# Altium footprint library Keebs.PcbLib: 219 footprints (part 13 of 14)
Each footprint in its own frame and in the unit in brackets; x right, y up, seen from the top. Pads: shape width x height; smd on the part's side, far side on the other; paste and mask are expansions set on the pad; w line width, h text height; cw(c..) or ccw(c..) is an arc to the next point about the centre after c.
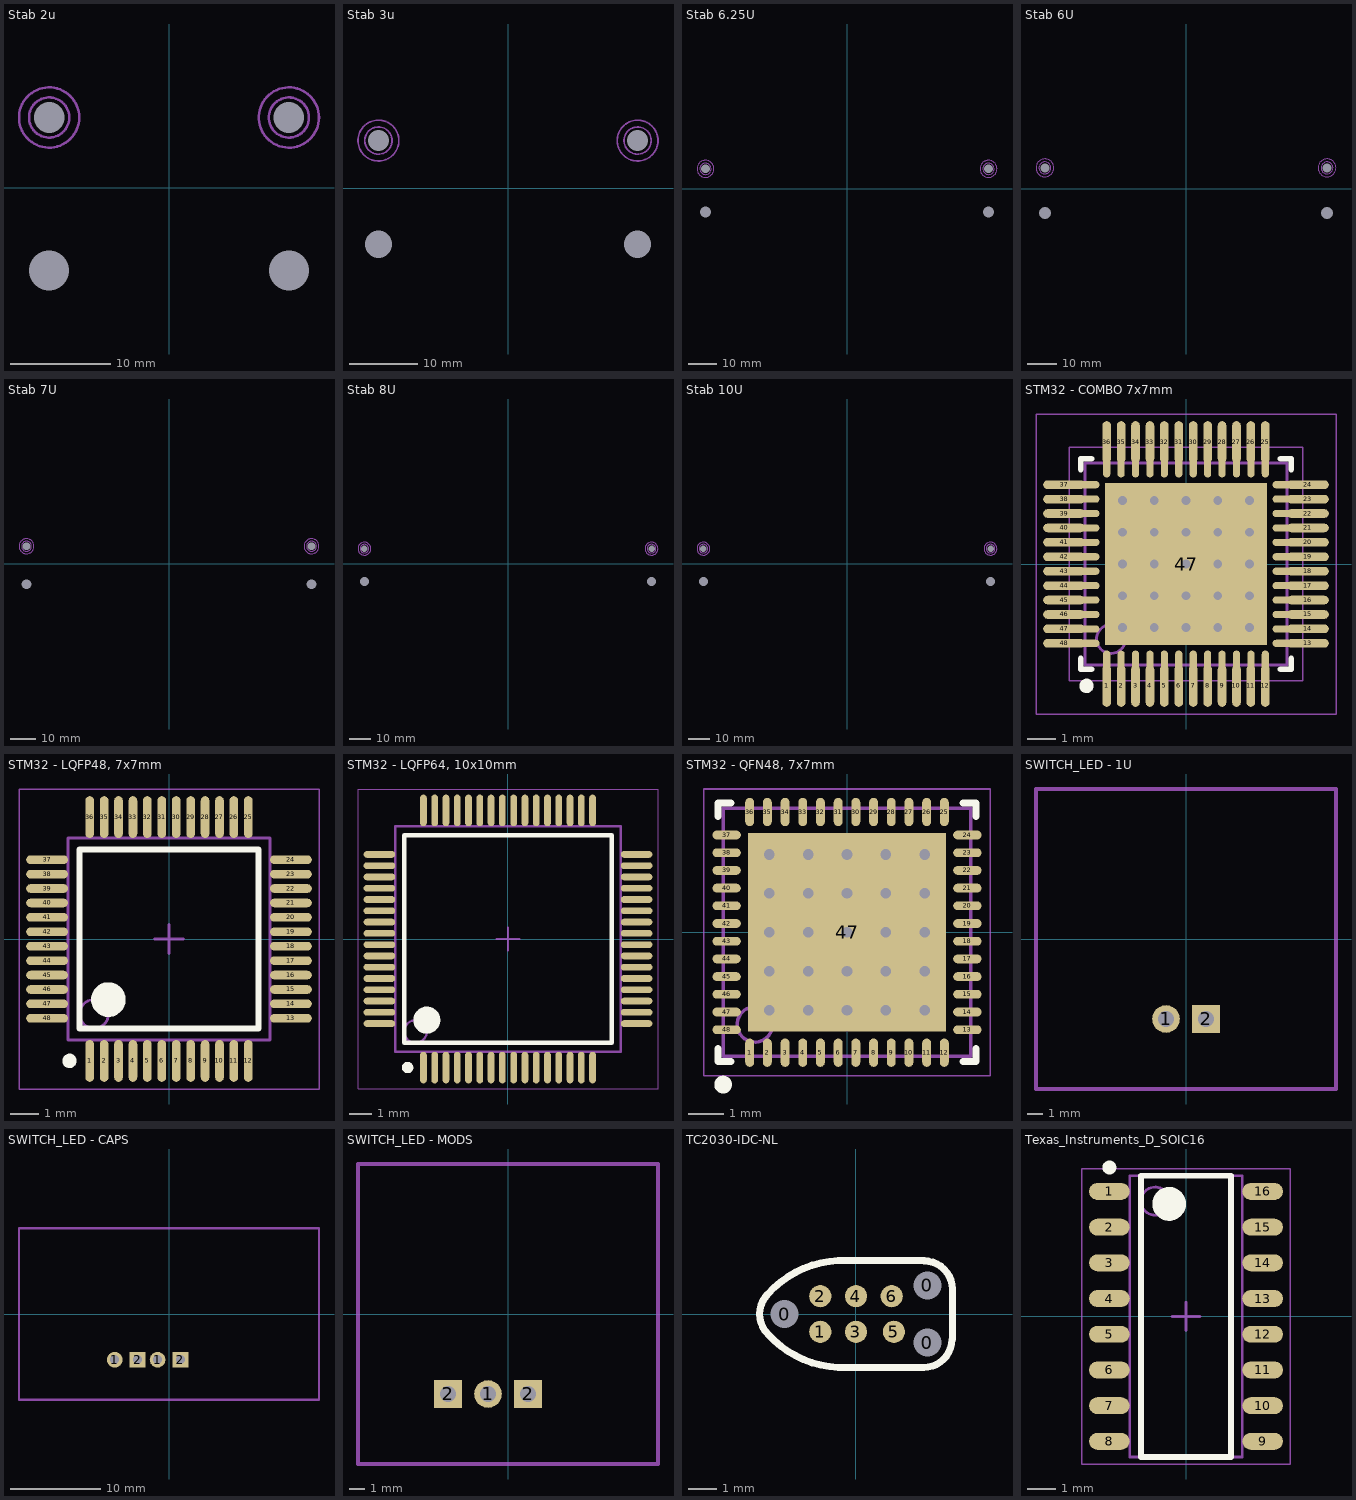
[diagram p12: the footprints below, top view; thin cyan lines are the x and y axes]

## Stab 2u [mil]
pads (6):
  round 60 hole 157.48 unplated: ""(-470,-325) ""(470,-325)
  round 60 hole 120 unplated: ""(-470,275) ""(470,275)
  round 39.37 on Mech13: ""(0,0) ""(0,0)
Mechanical 15:
  circle w10: c470,275 r118.11
  circle w10: c470,275 r78.74
  circle w10: c-470,275 r118.11
  circle w10: c-470,275 r78.74

## Stab 3u [mil]
pads (6):
  round 60 hole 157.48 unplated: ""(-750,-325) ""(750,-325)
  round 60 hole 120 unplated: ""(-750,275) ""(750,275)
  round 39.37 on Mech13: ""(0,0) ""(0,0)
Mechanical 15:
  circle w10: c-750,275 r118.11
  circle w10: c-750,275 r78.74
  circle w10: c750,275 r118.11
  circle w10: c750,275 r78.74

## Stab 6.25U [mil]
pads (5):
  round 60 hole 157.48 unplated: ""(-1968.5,-325) ""(1968.5,-325)
  round 60 hole 120 unplated: ""(-1968.5,275) ""(1968.5,275)
  round 39.37 on Mech13: ""(0,0)
Mechanical 15:
  circle w10: c-1968.5,275 r118.11
  circle w10: c-1968.5,275 r78.74
  circle w10: c1968.5,275 r118.11
  circle w10: c1968.5,275 r78.74

## Stab 6U [mil]
pads (5):
  round 60 hole 157.48 unplated: ""(-1870.08,-325) ""(1870.08,-325)
  round 60 hole 120 unplated: ""(-1870.08,275) ""(1870.08,275)
  round 39.37 on Mech13: ""(0,0)
Mechanical 15:
  circle w10: c1870.08,275 r78.74
  circle w10: c1870.08,275 r118.11
  circle w10: c-1870.08,275 r78.74
  circle w10: c-1870.08,275 r118.11

## Stab 7U [mil]
pads (5):
  round 60 hole 157.48 unplated: ""(-2250,-325) ""(2250,-325)
  round 60 hole 120 unplated: ""(-2250,275) ""(2250,275)
  round 39.37 on Mech13: ""(0,0)
Mechanical 15:
  circle w10: c-2250,275 r118.11
  circle w10: c-2250,275 r78.74
  circle w10: c2250,275 r118.11
  circle w10: c2250,275 r78.74

## Stab 8U [mil]
pads (5):
  round 60 hole 157.48 unplated: ""(-2625,-325) ""(2625,-325)
  round 60 hole 120 unplated: ""(-2625,275) ""(2625,275)
  round 39.37 on Mech13: ""(0,0)
Mechanical 15:
  circle w10: c2625,275 r78.74
  circle w10: c2625,275 r118.11
  circle w10: c-2625,275 r78.74
  circle w10: c-2625,275 r118.11

## Stab 10U [mil]
pads (5):
  round 60 hole 157.48 unplated: ""(-2625,-325) ""(2625,-325)
  round 60 hole 120 unplated: ""(-2625,275) ""(2625,275)
  round 39.37 on Mech13: ""(0,0)
Mechanical 15:
  circle w10: c2625,275 r78.74
  circle w10: c2625,275 r118.11
  circle w10: c-2625,275 r78.74
  circle w10: c-2625,275 r118.11

## STM32 - COMBO 7x7mm [mm] "LQFP48, 7x7mm"
height 1.6
pads (97):
  oval 0.3x1.45 smd paste-5: 1(-2.75,-4.225) 2(-2.25,-4.225) 3(-1.75,-4.225) 4(-1.25,-4.225) 5(-0.75,-4.225) 6(-0.25,-4.225) 7(0.25,-4.225) 8(0.75,-4.225) 9(1.25,-4.225) 10(1.75,-4.225) 11(2.25,-4.225) 12(2.75,-4.225) 25(2.75,4.225) 26(2.25,4.225) 27(1.75,4.225) 28(1.25,4.225) 29(0.75,4.225) 30(0.25,4.225) 31(-0.25,4.225) 32(-0.75,4.225) 33(-1.25,4.225) 34(-1.75,4.225) 35(-2.25,4.225) 36(-2.75,4.225)
  oval 0.25x0.8 smd: 1(-2.75,-3.4) 2(-2.25,-3.4) 3(-1.75,-3.4) 4(-1.25,-3.4) 5(-0.75,-3.4) 6(-0.25,-3.4) 7(0.25,-3.4) 8(0.75,-3.4) 9(1.25,-3.4) 10(1.75,-3.4) 11(2.25,-3.4) 12(2.75,-3.4) 25(2.75,3.4) 26(2.25,3.4) 27(1.75,3.4) 28(1.25,3.4) 29(0.75,3.4) 30(0.25,3.4) 31(-0.25,3.4) 32(-0.75,3.4) 33(-1.25,3.4) 34(-1.75,3.4) 35(-2.25,3.4) 36(-2.75,3.4)
  oval 0.8x0.25 smd: 13(3.4,-2.75) 14(3.4,-2.25) 15(3.4,-1.75) 16(3.4,-1.25) 17(3.4,-0.75) 18(3.4,-0.25) 19(3.4,0.25) 20(3.4,0.75) 21(3.4,1.25) 22(3.4,1.75) 23(3.4,2.25) 24(3.4,2.75) 37(-3.4,2.75) 38(-3.4,2.25) 39(-3.4,1.75) 40(-3.4,1.25) 41(-3.4,0.75) 42(-3.4,0.25) 43(-3.4,-0.25) 44(-3.4,-0.75) 45(-3.4,-1.25) 46(-3.4,-1.75) 47(-3.4,-2.25) 48(-3.4,-2.75)
  oval 1.45x0.3 smd paste-5: 13(4.225,-2.75) 14(4.225,-2.25) 15(4.225,-1.75) 16(4.225,-1.25) 17(4.225,-0.75) 18(4.225,-0.25) 19(4.225,0.25) 20(4.225,0.75) 21(4.225,1.25) 22(4.225,1.75) 23(4.225,2.25) 24(4.225,2.75) 37(-4.225,2.75) 38(-4.225,2.25) 39(-4.225,1.75) 40(-4.225,1.25) 41(-4.225,0.75) 42(-4.225,0.25) 43(-4.225,-0.25) 44(-4.225,-0.75) 45(-4.225,-1.25) 46(-4.225,-1.75) 47(-4.225,-2.25) 48(-4.225,-2.75)
  rect 5.6x5.6 smd: 47(0,0)
via -2.2,-1.1 diameter 0.6 hole 0.3
via -2.2,1.1 diameter 0.6 hole 0.3
via -1.1,-2.2 diameter 0.6 hole 0.3
via -1.1,0 diameter 0.6 hole 0.3
via -1.1,2.2 diameter 0.6 hole 0.3
via 0,-1.1 diameter 0.6 hole 0.3
via 0,1.1 diameter 0.6 hole 0.3
via 1.1,-2.2 diameter 0.6 hole 0.3
via 1.1,0 diameter 0.6 hole 0.3
via 1.1,2.2 diameter 0.6 hole 0.3
via 2.2,-1.1 diameter 0.6 hole 0.3
via 2.2,1.1 diameter 0.6 hole 0.3
via -2.2,-2.2 diameter 0.6 hole 0.3
via -2.2,0 diameter 0.6 hole 0.3
via -2.2,2.2 diameter 0.6 hole 0.3
via -1.1,-1.1 diameter 0.6 hole 0.3
via -1.1,1.1 diameter 0.6 hole 0.3
via 0,-2.2 diameter 0.6 hole 0.3
via 0,0 diameter 0.6 hole 0.3
via 0,2.2 diameter 0.6 hole 0.3
via 1.1,-1.1 diameter 0.6 hole 0.3
via 1.1,1.1 diameter 0.6 hole 0.3
via 2.2,-2.2 diameter 0.6 hole 0.3
via 2.2,0 diameter 0.6 hole 0.3
via 2.2,2.2 diameter 0.6 hole 0.3
Top Overlay:
  circle w0.25: c-3.45,-4.225 r0.125
  lines w0.2: -3.65,-3.275 -3.65,-3.65 -3.275,-3.65 ; -3.65,3.275 -3.65,3.65 -3.275,3.65 ; 3.275,-3.65 3.65,-3.65 3.65,-3.275 ; 3.275,3.65 3.65,3.65 3.65,3.275
Mechanical 13:
  circle w0.1: c-2.6,-2.6 r0.5
  circle w0.1: c-2.6,-2.6 r0.5
  lines w0.1: -3.5,-3.5 -3.5,3.5 ; -3.5,-3.5 3.5,-3.5 ; -3.5,-3.5 3.5,-3.5 ; -3.5,-3.5 -3.5,3.5 ; -3.5,3.5 3.5,3.5 ; -3.5,3.5 3.5,3.5 ; 3.5,-3.5 3.5,3.5 ; 3.5,-3.5 3.5,3.5
  text ".Designator" at 0.15,-1.806 h0.35
Mechanical 15:
  lines w0.05: -5.2,-5.2 -5.2,5.2 5.2,5.2 5.2,-5.2 -5.2,-5.2 ; -4.05,-4.05 4.05,-4.05 4.05,4.05 -4.05,4.05 -4.05,-4.05
  lines w0.1: -0.5,0 0.5,0 -0.5,0 ; 0,-0.5 0,0.5 0,-0.5
3D body "STM32 - QFN48, 7x7mm.step": height 0.5, standoff 0, extent -3.52,-3.52 3.52,3.52

## STM32 - LQFP48, 7x7mm [mm] "LQFP48, 7x7mm"
height 1.6
pads (48):
  oval 0.3x1.45 smd: 1(-2.75,-4.225) 2(-2.25,-4.225) 3(-1.75,-4.225) 4(-1.25,-4.225) 5(-0.75,-4.225) 6(-0.25,-4.225) 7(0.25,-4.225) 8(0.75,-4.225) 9(1.25,-4.225) 10(1.75,-4.225) 11(2.25,-4.225) 12(2.75,-4.225) 25(2.75,4.225) 26(2.25,4.225) 27(1.75,4.225) 28(1.25,4.225) 29(0.75,4.225) 30(0.25,4.225) 31(-0.25,4.225) 32(-0.75,4.225) 33(-1.25,4.225) 34(-1.75,4.225) 35(-2.25,4.225) 36(-2.75,4.225)
  oval 1.45x0.3 smd: 13(4.225,-2.75) 14(4.225,-2.25) 15(4.225,-1.75) 16(4.225,-1.25) 17(4.225,-0.75) 18(4.225,-0.25) 19(4.225,0.25) 20(4.225,0.75) 21(4.225,1.25) 22(4.225,1.75) 23(4.225,2.25) 24(4.225,2.75) 37(-4.225,2.75) 38(-4.225,2.25) 39(-4.225,1.75) 40(-4.225,1.25) 41(-4.225,0.75) 42(-4.225,0.25) 43(-4.225,-0.25) 44(-4.225,-0.75) 45(-4.225,-1.25) 46(-4.225,-1.75) 47(-4.225,-2.25) 48(-4.225,-2.75)
Top Overlay:
  circle w0.6: c-2.1,-2.1 r0.3
  circle w0.25: c-3.45,-4.225 r0.125
  lines w0.2: -3.1,-3.1 -3.1,3.1 3.1,3.1 3.1,-3.1 -3.1,-3.1
Mechanical 13:
  circle w0.1: c-2.6,-2.6 r0.5
  lines w0.1: -3.5,-3.5 -3.5,3.5 3.5,3.5 3.5,-3.5 -3.5,-3.5
  text ".Designator" at 0.15,-1.806 h0.35
Mechanical 15:
  lines w0.05: -5.2,-5.2 -5.2,5.2 5.2,5.2 5.2,-5.2 -5.2,-5.2
  lines w0.1: -0.5,0 0.5,0 ; 0,-0.5 0,0.5
3D body "STM32F072.step": height 1.6, standoff 0, extent -4.5,-4.5 4.5,4.5

## STM32 - LQFP64, 10x10mm [mm] "TSQFP, 64-Leads, Body 10.00x10.00mm, Pitch 0.50mm, IPC Medium Density"
height 1.5
pads (64):
  oval 0.3x1.4 smd: 1(-3.75,-5.7) 2(-3.25,-5.7) 3(-2.75,-5.7) 4(-2.25,-5.7) 5(-1.75,-5.7) 6(-1.25,-5.7) 7(-0.75,-5.7) 8(-0.25,-5.7) 9(0.25,-5.7) 10(0.75,-5.7) 11(1.25,-5.7) 12(1.75,-5.7) 13(2.25,-5.7) 14(2.75,-5.7) 15(3.25,-5.7) 16(3.75,-5.7) 33(3.75,5.7) 34(3.25,5.7) 35(2.75,5.7) 36(2.25,5.7) 37(1.75,5.7) 38(1.25,5.7) 39(0.75,5.7) 40(0.25,5.7) 41(-0.25,5.7) 42(-0.75,5.7) 43(-1.25,5.7) 44(-1.75,5.7) 45(-2.25,5.7) 46(-2.75,5.7) 47(-3.25,5.7) 48(-3.75,5.7)
  oval 1.4x0.3 smd: 17(5.7,-3.75) 18(5.7,-3.25) 19(5.7,-2.75) 20(5.7,-2.25) 21(5.7,-1.75) 22(5.7,-1.25) 23(5.7,-0.75) 24(5.7,-0.25) 25(5.7,0.25) 26(5.7,0.75) 27(5.7,1.25) 28(5.7,1.75) 29(5.7,2.25) 30(5.7,2.75) 31(5.7,3.25) 32(5.7,3.75) 49(-5.7,3.75) 50(-5.7,3.25) 51(-5.7,2.75) 52(-5.7,2.25) 53(-5.7,1.75) 54(-5.7,1.25) 55(-5.7,0.75) 56(-5.7,0.25) 57(-5.7,-0.25) 58(-5.7,-0.75) 59(-5.7,-1.25) 60(-5.7,-1.75) 61(-5.7,-2.25) 62(-5.7,-2.75) 63(-5.7,-3.25) 64(-5.7,-3.75)
Top Overlay:
  circle w0.25: c-4.45,-5.7 r0.125
  circle w0.6: c-3.6,-3.6 r0.3
  lines w0.2: -4.6,-4.6 4.6,-4.6 4.6,4.6 -4.6,4.6 -4.6,-4.6
Mechanical 13:
  circle w0.1: c-4.1,-4.1 r0.5
  lines w0.1: -5,-5 5,-5 5,5 -5,5 -5,-5
  text ".Designator" at 0.15,-1.806 h0.35
Mechanical 15:
  lines w0.05: -6.65,-6.65 6.65,-6.65 6.65,6.65 -6.65,6.65 -6.65,-6.65
  lines w0.1: -0.5,0 0.5,0 ; 0,-0.5 0,0.5
3D body "STM32 - LQFP64, 10x10mm.step": height 1.5, standoff 0, extent -6,-6 6,6

## STM32 - QFN48, 7x7mm [mm] "QFN, 48-Leads, Body 6,95x6,95mm, Pitch 0,50mm, Thermal Pad 5,60x5,60mm, IPC Medium Density"
height 0.5
pads (49):
  oval 0.25x0.8 smd: 1(-2.75,-3.4) 2(-2.25,-3.4) 3(-1.75,-3.4) 4(-1.25,-3.4) 5(-0.75,-3.4) 6(-0.25,-3.4) 7(0.25,-3.4) 8(0.75,-3.4) 9(1.25,-3.4) 10(1.75,-3.4) 11(2.25,-3.4) 12(2.75,-3.4) 25(2.75,3.4) 26(2.25,3.4) 27(1.75,3.4) 28(1.25,3.4) 29(0.75,3.4) 30(0.25,3.4) 31(-0.25,3.4) 32(-0.75,3.4) 33(-1.25,3.4) 34(-1.75,3.4) 35(-2.25,3.4) 36(-2.75,3.4)
  oval 0.8x0.25 smd: 13(3.4,-2.75) 14(3.4,-2.25) 15(3.4,-1.75) 16(3.4,-1.25) 17(3.4,-0.75) 18(3.4,-0.25) 19(3.4,0.25) 20(3.4,0.75) 21(3.4,1.25) 22(3.4,1.75) 23(3.4,2.25) 24(3.4,2.75) 37(-3.4,2.75) 38(-3.4,2.25) 39(-3.4,1.75) 40(-3.4,1.25) 41(-3.4,0.75) 42(-3.4,0.25) 43(-3.4,-0.25) 44(-3.4,-0.75) 45(-3.4,-1.25) 46(-3.4,-1.75) 47(-3.4,-2.25) 48(-3.4,-2.75)
  rect 5.6x5.6 smd: 47(0,0)
via 2.2,2.2 diameter 0.6 hole 0.3
via 2.2,1.1 diameter 0.6 hole 0.3
via 2.2,0 diameter 0.6 hole 0.3
via 2.2,-1.1 diameter 0.6 hole 0.3
via 2.2,-2.2 diameter 0.6 hole 0.3
via 1.1,2.2 diameter 0.6 hole 0.3
via 1.1,1.1 diameter 0.6 hole 0.3
via 1.1,0 diameter 0.6 hole 0.3
via 1.1,-1.1 diameter 0.6 hole 0.3
via 1.1,-2.2 diameter 0.6 hole 0.3
via 0,2.2 diameter 0.6 hole 0.3
via 0,1.1 diameter 0.6 hole 0.3
via 0,0 diameter 0.6 hole 0.3
via 0,-1.1 diameter 0.6 hole 0.3
via 0,-2.2 diameter 0.6 hole 0.3
via -1.1,2.2 diameter 0.6 hole 0.3
via -1.1,1.1 diameter 0.6 hole 0.3
via -1.1,0 diameter 0.6 hole 0.3
via -1.1,-1.1 diameter 0.6 hole 0.3
via -1.1,-2.2 diameter 0.6 hole 0.3
via -2.2,2.2 diameter 0.6 hole 0.3
via -2.2,1.1 diameter 0.6 hole 0.3
via -2.2,0 diameter 0.6 hole 0.3
via -2.2,-1.1 diameter 0.6 hole 0.3
via -2.2,-2.2 diameter 0.6 hole 0.3
Top Overlay:
  circle w0.25: c-3.5,-4.3 r0.125
  lines w0.2: -3.65,-3.275 -3.65,-3.65 -3.275,-3.65 ; -3.65,3.275 -3.65,3.65 -3.275,3.65 ; 3.275,-3.65 3.65,-3.65 3.65,-3.275 ; 3.275,3.65 3.65,3.65 3.65,3.275
Mechanical 13:
  circle w0.1: c-2.6,-2.6 r0.5
  lines w0.1: -3.5,-3.5 -3.5,3.5 3.5,3.5 3.5,-3.5 -3.5,-3.5
  text ".Designator" at -0.485,-1.552 h0.35
Mechanical 15:
  lines w0.05: -4.05,-4.05 -4.05,4.05 4.05,4.05 4.05,-4.05 -4.05,-4.05
  lines w0.1: -0.5,0 0.5,0 ; 0,-0.5 0,0.5
3D body "STM32 - QFN48, 7x7mm.step": height 0.5, standoff 0, extent -3.52,-3.52 3.52,3.52

## SWITCH_LED - 1U [mm]
pads (3):
  round 1.75 hole 1 mask-0.4: 1(-1.27,-5.08)
  rect 1.75x1.75 hole 1 mask-0.7: 2(1.27,-5.08)
  round 1 on Mech13: ""(0,0)
Mechanical 13:
  lines w0.254: -9.525,-9.525 -9.525,9.525 9.525,9.525 9.525,-9.525 -9.525,-9.525
  text ".Designator" at -3.575,-3.7 h0.7

## SWITCH_LED - CAPS [mm]
pads (5):
  round 1.75 hole 1 mask-0.4: 1(-6.032,-5.08) 1(-1.27,-5.08)
  rect 1.75x1.75 hole 1 mask-0.7: 2(-3.492,-5.08) 2(1.27,-5.08)
  round 1 on Mech13: ""(0,0)
Mechanical 13:
  lines w0.254: -16.669,-9.525 -16.669,9.525 16.669,9.525 16.669,-9.525 ; -16.669,-9.525 16.669,-9.525 ; -16.669,-9.525 16.669,-9.525
  text ".Designator" at -7.85,-7.5 h0.7

## SWITCH_LED - MODS [mm]
pads (4):
  round 1.75 hole 1 mask-0.4: 1(-1.27,-5.08)
  rect 1.75x1.75 hole 1 mask-0.7: 2(-3.81,-5.08) 2(1.27,-5.08)
  round 1 on Mech13: ""(0,0)
Mechanical 13:
  lines w0.254: -9.525,-9.525 -9.525,9.525 9.525,9.525 9.525,-9.525 -9.525,-9.525
  text ".Designator" at -3.575,-3.7 h0.7

## TC2030-IDC-NL [mm] "Tag-Connect 6-Pin with No Legs (PN# TC2030-IDC-NL)"
pads (9):
  round 0.9 hole 0.995 unplated: 0(-2.54,0) 0(2.54,-1.016) 0(2.54,1.016)
  round 0.79 smd paste-0.39: 1(-1.27,-0.635) 2(-1.27,0.635) 3(0,-0.635) 4(0,0.635) 5(1.35,-0.635) 6(1.27,0.635)
Top Overlay:
  lines w0.254: -0.635,-1.905 cw(c-0.445,1.714) -3.129,-0.72 cw(c-2.415,0) -3.135,0.714 cw(c-0.445,-1.714) -0.635,1.905 ; -0.635,-1.9 2.413,-1.9 ; -0.635,1.9 2.429,1.9 ; 2.413,-1.905 ccw(c2.413,-0.905) 3.413,-0.905 ; 2.429,1.889 cw(c2.429,0.889) 3.429,0.889 3.429,-0.905

## Texas_Instruments_D_SOIC16 [mm]
height 1.75
pads (16):
  oval 1.45x0.6 smd: 1(-2.725,4.445) 2(-2.725,3.175) 3(-2.725,1.905) 4(-2.725,0.635) 5(-2.725,-0.635) 6(-2.725,-1.905) 7(-2.725,-3.175) 8(-2.725,-4.445) 9(2.725,-4.445) 10(2.725,-3.175) 11(2.725,-1.905) 12(2.725,-0.635) 13(2.725,0.635) 14(2.725,1.905) 15(2.725,3.175) 16(2.725,4.445)
Top Overlay:
  circle w0.25: c-2.725,5.295 r0.125
  circle w0.6: c-0.6,4 r0.3
  lines w0.2: -1.6,-5 -1.6,5 1.6,5 1.6,-5 -1.6,-5
Mechanical 13:
  circle w0.1: c-1.1,4.1 r0.5
  lines w0.1: -2,-5 -2,5 2,5 2,-5 -2,-5
  text ".Designator" at -0.356,1.575 h0.7
Mechanical 15:
  lines w0.05: -3.7,-5.25 -3.7,5.25 3.7,5.25 3.7,-5.25 -3.7,-5.25
  lines w0.1: -0.5,0 0.5,0 ; 0,-0.5 0,0.5
3D body "Texas_Instruments_D_SOIC16.step": height 1.75, standoff 0, extent -3,-5 3,5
